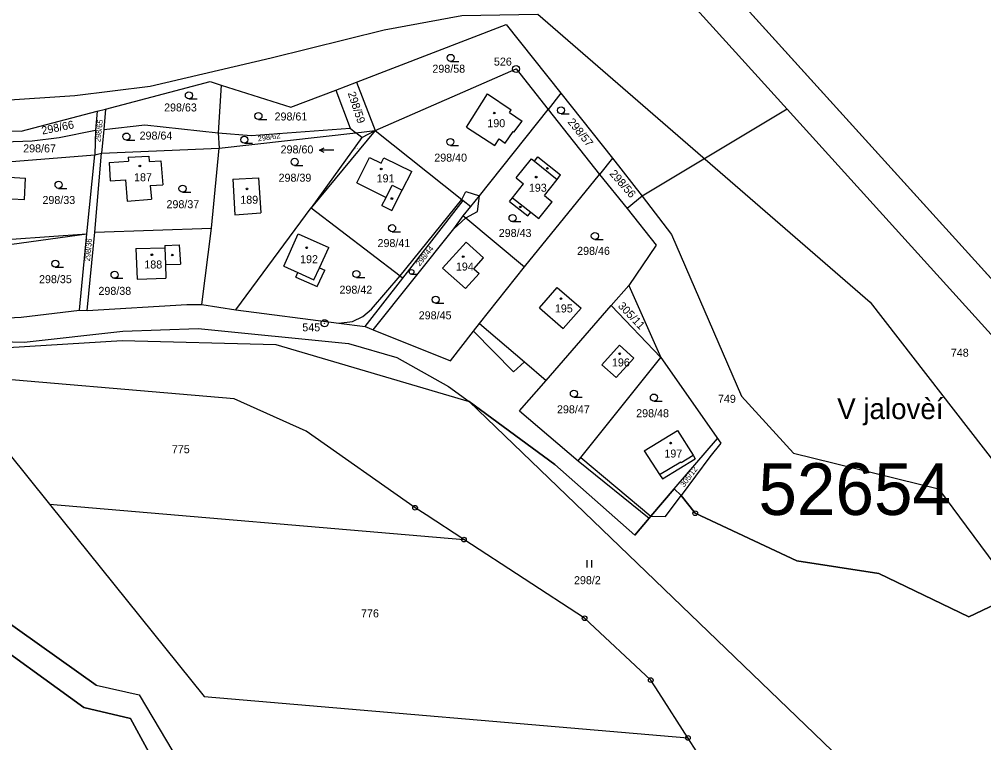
# Model space of a CAD drawing. Extents: x -725765 to -723182, y -1052705 to -1049154.
# Drawn here: x -723752.1 to -723547.3, y -1051559.5 to -1051405.8 of the extents above; entities that cross this region are included whole.
import ezdxf

# ---------------------------------------------------------------- set-up
doc = ezdxf.new("R2010")
doc.units = 0
for name, color, linetype in [('Vrstva 1', 7, 'Continuous'), ('Vrstva 13', 7, 'Continuous'), ('Vrstva 15', 7, 'Continuous'), ('Vrstva 16', 7, 'Continuous'), ('Vrstva 17', 7, 'Continuous'), ('Vrstva 18', 7, 'Continuous'), ('Vrstva 19', 7, 'Continuous'), ('Vrstva 25', 7, 'Continuous'), ('Vrstva 4', 7, 'Continuous'), ('Vrstva 52', 7, 'Continuous'), ('Vrstva 53', 7, 'Continuous')]:
    doc.layers.add(name, color=color, linetype=linetype)

msp = doc.modelspace()

# ---------------------------------------------------------------- linework, layer by layer
at = {"layer": 'Vrstva 1'}
for points in [[(-723589.08, -1051424.9), (-723679.72, -1051324.79)], [(-723680.51, -1051419.11), (-723648.75, -1051406.89)], [(-723648.75, -1051406.89), (-723637.16, -1051421.5)], [(-723676.57, -1051429.42), (-723646.65, -1051416.34)], [(-723646.65, -1051416.34), (-723639.87, -1051424.92)], [(-723733.84, -1051424.85), (-723711.6, -1051419.02)], [(-723711.6, -1051419.02), (-723709.27, -1051419.76)], [(-723709.27, -1051419.76), (-723709.93, -1051429.92)], [(-723709.27, -1051419.76), (-723694.45, -1051424.48)], [(-723684.94, -1051420.82), (-723680.51, -1051419.11)], [(-723680.51, -1051419.11), (-723676.57, -1051429.42)], [(-723694.45, -1051424.48), (-723684.94, -1051420.82)], [(-723684.94, -1051420.82), (-723681.85, -1051428.93)], [(-723657.21, -1051428.67), (-723652.73, -1051421.59)], [(-723652.73, -1051421.59), (-723647.66, -1051424.99)], [(-723637.16, -1051421.5), (-723639.87, -1051424.92)], [(-723637.16, -1051421.5), (-723626.2, -1051435.31)], [(-723751.73, -1051429.55), (-723735.61, -1051425.32)], [(-723735.61, -1051425.32), (-723735.96, -1051429.31)], [(-723735.61, -1051425.32), (-723733.84, -1051424.85)], [(-723733.84, -1051424.85), (-723734.2, -1051429.17)], [(-723654.45, -1051443.3), (-723639.87, -1051424.92)], [(-723648.06, -1051425.57), (-723647.66, -1051424.99)], [(-723648.06, -1051425.57), (-723645.35, -1051427.39)], [(-723639.87, -1051424.92), (-723628.93, -1051438.73)], [(-723589.08, -1051424.9), (-723619.84, -1051443.33)], [(-723512.61, -1051509.36), (-723589.08, -1051424.9)], [(-723734.2, -1051429.17), (-723725.45, -1051428.18)], [(-723725.45, -1051428.18), (-723709.93, -1051429.92)], [(-723657.21, -1051428.67), (-723651.18, -1051432.56)], [(-723647.12, -1051429.76), (-723645.35, -1051427.39)], [(-723759.26, -1051429.49), (-723751.73, -1051429.55)], [(-723743.64, -1051430.89), (-723735.96, -1051429.31)], [(-723735.96, -1051429.31), (-723736.13, -1051434.61)], [(-723734.2, -1051429.17), (-723734.65, -1051434.25)], [(-723709.93, -1051429.92), (-723709.67, -1051433.14)], [(-723709.93, -1051429.92), (-723702.92, -1051430.44)], [(-723709.67, -1051433.14), (-723680.68, -1051429.88)], [(-723702.92, -1051430.44), (-723681.85, -1051428.93)], [(-723676.57, -1051429.42), (-723690.19, -1051445.83)], [(-723681.85, -1051428.93), (-723680.68, -1051429.88)], [(-723680.68, -1051429.88), (-723676.57, -1051429.42)], [(-723679.41, -1051430.91), (-723680.68, -1051429.88)], [(-723676.57, -1051429.42), (-723658.16, -1051444.07)], [(-723648.96, -1051432.13), (-723647.29, -1051429.65)], [(-723647.29, -1051429.65), (-723647.12, -1051429.76)], [(-723759.54, -1051431.99), (-723749.44, -1051431.61)], [(-723749.44, -1051431.61), (-723743.64, -1051430.89)], [(-723679.41, -1051430.91), (-723690.19, -1051445.83)], [(-723651.18, -1051432.56), (-723650.22, -1051431.15)], [(-723650.22, -1051431.15), (-723648.96, -1051432.13)], [(-723760.04, -1051436.48), (-723736.13, -1051434.61)], [(-723737.77, -1051451.4), (-723736.13, -1051434.61)], [(-723736.13, -1051451.04), (-723734.65, -1051434.25)], [(-723736.13, -1051434.61), (-723734.65, -1051434.25)], [(-723734.65, -1051434.25), (-723709.67, -1051433.14)], [(-723729, -1051435.04), (-723724.66, -1051434.83)], [(-723724.66, -1051434.83), (-723724.59, -1051435.98)], [(-723710.18, -1051438.34), (-723709.67, -1051433.14)], [(-723733.09, -1051436.24), (-723728.93, -1051435.89)], [(-723733.09, -1051436.24), (-723732.85, -1051440.12)], [(-723729, -1051435.04), (-723728.93, -1051435.89)], [(-723724.59, -1051435.98), (-723722.05, -1051435.83)], [(-723722.05, -1051435.83), (-723721.68, -1051440.98)], [(-723680.44, -1051440.51), (-723677.75, -1051435.15)], [(-723677.75, -1051435.15), (-723675.3, -1051436.37)], [(-723675.3, -1051436.37), (-723674.71, -1051435.19)], [(-723674.71, -1051435.19), (-723668.79, -1051438.12)], [(-723646.62, -1051439.49), (-723643.38, -1051435.4)], [(-723643.38, -1051435.4), (-723642.76, -1051435.9)], [(-723642.76, -1051435.9), (-723642.03, -1051435.01)], [(-723642.03, -1051435.01), (-723637.19, -1051438.84)], [(-723626.2, -1051435.31), (-723628.93, -1051438.73)], [(-723626.2, -1051435.31), (-723619.84, -1051443.33)], [(-723711.34, -1051450.16), (-723710.18, -1051438.34)], [(-723670.84, -1051442.12), (-723668.79, -1051438.12)], [(-723644.88, -1051458.37), (-723628.93, -1051438.73)], [(-723637.95, -1051439.81), (-723637.19, -1051438.84)], [(-723628.93, -1051438.73), (-723623.06, -1051445.95)], [(-723759.19, -1051439.04), (-723750.8, -1051439.52)], [(-723751.05, -1051444.1), (-723750.8, -1051439.52)], [(-723732.85, -1051440.12), (-723729.56, -1051439.89)], [(-723729.56, -1051439.89), (-723729.25, -1051444.41)], [(-723724.33, -1051441.09), (-723721.68, -1051440.98)], [(-723706.82, -1051439.76), (-723701.32, -1051439.44)], [(-723706.82, -1051439.76), (-723706.4, -1051447.36)], [(-723701.32, -1051439.44), (-723700.88, -1051446.93)], [(-723680.44, -1051440.51), (-723674.24, -1051443.63)], [(-723647.41, -1051443.68), (-723645.05, -1051440.75)], [(-723646.62, -1051439.49), (-723645.05, -1051440.75)], [(-723640.63, -1051443.24), (-723637.95, -1051439.81)], [(-723724.33, -1051441.09), (-723724.08, -1051443.97)], [(-723673.03, -1051446.38), (-723670.84, -1051442.12)], [(-723753.78, -1051443.91), (-723751.05, -1051444.1)], [(-723729.25, -1051444.41), (-723724.08, -1051443.97)], [(-723675.13, -1051445.31), (-723674.24, -1051443.63)], [(-723670.69, -1051460.75), (-723657.86, -1051444.31)], [(-723658.16, -1051444.07), (-723657.86, -1051444.31)], [(-723657.86, -1051444.31), (-723656.29, -1051445.56)], [(-723656.29, -1051445.56), (-723654.45, -1051443.3)], [(-723648.03, -1051444.46), (-723647.41, -1051443.68)], [(-723648.03, -1051444.46), (-723644.15, -1051447.53)], [(-723641.79, -1051448.12), (-723638.97, -1051444.55)], [(-723640.63, -1051443.24), (-723638.97, -1051444.55)], [(-723619.84, -1051443.33), (-723623.06, -1051445.95)], [(-723619.84, -1051443.33), (-723613.68, -1051451.51)], [(-723706.4, -1051447.36), (-723700.88, -1051446.93)], [(-723706.16, -1051467.53), (-723690.19, -1051445.83)], [(-723690.19, -1051445.83), (-723671.28, -1051460.3)], [(-723675.13, -1051445.31), (-723673.03, -1051446.38)], [(-723657.89, -1051447.51), (-723656.29, -1051445.56)], [(-723644.15, -1051447.53), (-723643.51, -1051446.76)], [(-723643.51, -1051446.76), (-723641.79, -1051448.12)], [(-723623.06, -1051445.95), (-723616.9, -1051453.76)], [(-723659.87, -1051450.29), (-723657.89, -1051447.51)], [(-723657.89, -1051447.51), (-723657.32, -1051447.99)], [(-723657.32, -1051447.99), (-723644.88, -1051458.37)], [(-723737.7, -1051467.62), (-723736.13, -1051451.04)], [(-723736.13, -1051451.04), (-723711.34, -1051450.16)], [(-723713.36, -1051466.39), (-723711.34, -1051450.16)], [(-723677.03, -1051471.79), (-723659.87, -1051450.29)], [(-723761.87, -1051453.08), (-723737.77, -1051451.4)], [(-723739.33, -1051467.58), (-723737.77, -1051451.4)], [(-723695.95, -1051458.23), (-723692.95, -1051451.37)], [(-723692.95, -1051451.37), (-723686.44, -1051454.27)], [(-723662.24, -1051458.63), (-723657.27, -1051453.12)], [(-723657.27, -1051453.12), (-723653.54, -1051456.45)], [(-723613.68, -1051451.51), (-723598.78, -1051485.83)], [(-723727.37, -1051454.51), (-723721.23, -1051454.36)], [(-723727.37, -1051454.51), (-723727.14, -1051460.98)], [(-723721.25, -1051453.81), (-723718.2, -1051453.72)], [(-723721.25, -1051453.81), (-723721.23, -1051454.36)], [(-723718.2, -1051453.72), (-723717.93, -1051457.8)], [(-723688.4, -1051458.58), (-723686.44, -1051454.27)], [(-723616.9, -1051453.76), (-723622.72, -1051462.36)], [(-723655.63, -1051458.78), (-723653.54, -1051456.45)], [(-723721.12, -1051457.9), (-723717.93, -1051457.8)], [(-723721.12, -1051457.9), (-723721.03, -1051460.79)], [(-723695.95, -1051458.23), (-723692.97, -1051459.61)], [(-723688.91, -1051462.57), (-723687.27, -1051459.05)], [(-723688.4, -1051458.58), (-723687.27, -1051459.05)], [(-723662.24, -1051458.63), (-723657.37, -1051462.96)], [(-723655.63, -1051458.78), (-723654.51, -1051459.79)], [(-723654.41, -1051470.42), (-723644.88, -1051458.37)], [(-723727.14, -1051460.98), (-723721.03, -1051460.79)], [(-723693.44, -1051460.54), (-723692.97, -1051459.61)], [(-723693.44, -1051460.54), (-723688.91, -1051462.57)], [(-723678.72, -1051471.04), (-723670.69, -1051460.75)], [(-723671.28, -1051460.3), (-723670.69, -1051460.75)], [(-723657.37, -1051462.96), (-723654.51, -1051459.79)], [(-723641.7, -1051467.11), (-723637.91, -1051462.78)], [(-723637.91, -1051462.78), (-723632.86, -1051467.14)], [(-723626.47, -1051466.56), (-723622.72, -1051462.36)], [(-723622.72, -1051462.36), (-723615.88, -1051477.67)], [(-723751.71, -1051469.1), (-723739.33, -1051467.58)], [(-723739.33, -1051467.58), (-723737.7, -1051467.62)], [(-723737.7, -1051467.62), (-723716.54, -1051466.37)], [(-723716.54, -1051466.37), (-723713.36, -1051466.39)], [(-723713.36, -1051466.39), (-723706.16, -1051467.53)], [(-723706.16, -1051467.53), (-723684.3, -1051470.33)], [(-723641.7, -1051467.11), (-723636.68, -1051471.5)], [(-723640.24, -1051482.51), (-723626.47, -1051466.56)], [(-723636.68, -1051471.5), (-723632.86, -1051467.14)], [(-723626.47, -1051466.56), (-723615.88, -1051477.67)], [(-723763.16, -1051469.61), (-723751.71, -1051469.1)], [(-723730.17, -1051472.08), (-723714.13, -1051471.46)], [(-723714.13, -1051471.46), (-723682.21, -1051474.64)], [(-723684.3, -1051470.33), (-723678.72, -1051471.04)], [(-723678.72, -1051471.04), (-723677.03, -1051471.79)], [(-723655.7, -1051472.07), (-723654.41, -1051470.42)], [(-723654.41, -1051470.42), (-723644.83, -1051478.59)], [(-723751.13, -1051474.35), (-723730.17, -1051472.08)], [(-723677.03, -1051471.79), (-723660.56, -1051478.32)], [(-723660.56, -1051478.32), (-723655.7, -1051472.07)], [(-723770.72, -1051476.53), (-723730.31, -1051474.06)], [(-723763.53, -1051474.03), (-723751.13, -1051474.35)], [(-723730.31, -1051474.06), (-723697.64, -1051474.89)], [(-723697.64, -1051474.89), (-723656.62, -1051487.01)], [(-723682.21, -1051474.64), (-723671.97, -1051477.65)], [(-723628.47, -1051479.21), (-723624.71, -1051475.01)], [(-723624.71, -1051475.01), (-723621.65, -1051477.8)], [(-723671.97, -1051477.65), (-723661, -1051483.8)], [(-723632.89, -1051498.9), (-723615.88, -1051477.67)], [(-723625.37, -1051481.88), (-723621.65, -1051477.8)], [(-723615.88, -1051477.67), (-723603.14, -1051495.87)], [(-723644.83, -1051478.59), (-723640.24, -1051482.51)], [(-723628.47, -1051479.21), (-723625.37, -1051481.88)], [(-723767.94, -1051481.2), (-723745.73, -1051508.83)], [(-723706.54, -1051486.44), (-723767.94, -1051481.2)], [(-723661, -1051483.8), (-723656.62, -1051487.01)], [(-723645.9, -1051489), (-723640.24, -1051482.51)], [(-723598.78, -1051485.83), (-723587.77, -1051497.95)], [(-723691.23, -1051493.31), (-723706.54, -1051486.44)], [(-723656.62, -1051487.01), (-723638.4, -1051500.35)], [(-723656.62, -1051487.01), (-723575.76, -1051564.86)], [(-723645.9, -1051489), (-723633.43, -1051499.58)], [(-723668.1, -1051509.58), (-723691.23, -1051493.31)], [(-723619.47, -1051497.5), (-723612.4, -1051493.13)], [(-723612.4, -1051493.13), (-723609.06, -1051498.41)], [(-723613.05, -1051505.55), (-723603.87, -1051494.83)], [(-723603.14, -1051495.87), (-723605.49, -1051498.72)], [(-723603.87, -1051494.83), (-723603.14, -1051495.87)], [(-723619.47, -1051497.5), (-723616.19, -1051502.47)], [(-723587.77, -1051497.95), (-723556.95, -1051505.58)], [(-723638.4, -1051500.35), (-723621.46, -1051515.37)], [(-723633.43, -1051499.58), (-723632.89, -1051498.9)], [(-723633.43, -1051499.58), (-723618.41, -1051511.81)], [(-723615.55, -1051503.44), (-723608.6, -1051499.14)], [(-723605.49, -1051498.72), (-723611.59, -1051506.99)], [(-723609.06, -1051498.41), (-723608.6, -1051499.14)], [(-723616.19, -1051502.47), (-723615.55, -1051503.44)], [(-723618.04, -1051511.38), (-723613.05, -1051505.55)], [(-723613.05, -1051505.55), (-723611.59, -1051506.99)], [(-723556.95, -1051505.58), (-723540.54, -1051527.73)], [(-723611.59, -1051506.99), (-723608.62, -1051510.73)], [(-723745.73, -1051508.83), (-723712.87, -1051549.7)], [(-723745.73, -1051508.83), (-723657.72, -1051516.34)], [(-723665.77, -1051511.09), (-723668.1, -1051509.58)], [(-723657.72, -1051516.34), (-723665.77, -1051511.09)], [(-723621.46, -1051515.37), (-723618.41, -1051511.81)], [(-723618.41, -1051511.81), (-723618.04, -1051511.38)], [(-723608.62, -1051510.73), (-723587.06, -1051520.84)], [(-723632.09, -1051533.05), (-723657.72, -1051516.34)], [(-723587.06, -1051520.84), (-723569.65, -1051523.55)], [(-723569.65, -1051523.55), (-723550.5, -1051532.75)], [(-723735.81, -1051547.23), (-723760.44, -1051529.74)], [(-723550.5, -1051532.75), (-723544.71, -1051530.01)], [(-723618.06, -1051546.2), (-723632.09, -1051533.05)], [(-723738.43, -1051552.03), (-723761.92, -1051534.99)], [(-723735.81, -1051547.23), (-723726.68, -1051549.29)], [(-723616.36, -1051548.82), (-723618.06, -1051546.2)], [(-723726.68, -1051549.29), (-723706.61, -1051583.2)], [(-723610.16, -1051558.47), (-723616.36, -1051548.82)], [(-723712.87, -1051549.7), (-723610.16, -1051558.47)], [(-723728.55, -1051554.37), (-723738.43, -1051552.03)], [(-723711.06, -1051586.5), (-723728.55, -1051554.37)], [(-723601.23, -1051572.36), (-723610.16, -1051558.47)]]:
    msp.add_lwpolyline(points, dxfattribs=at)
at = {"layer": 'Vrstva 13'}
msp.add_lwpolyline([(-723506.17, -1051504.56), (-723672.97, -1051320.32)], dxfattribs=at)
at = {"layer": 'Vrstva 25'}
for points in [[(-723660.54, -1051414.73), (-723658.79, -1051414.73)], [(-723716.13, -1051422.69), (-723714.38, -1051422.69)], [(-723637.1, -1051425.87), (-723635.35, -1051425.87)], [(-723701.36, -1051427.07), (-723699.61, -1051427.07)], [(-723729.39, -1051431.44), (-723727.64, -1051431.44)], [(-723704.35, -1051432.11), (-723702.6, -1051432.11)], [(-723660.6, -1051432.59), (-723658.85, -1051432.59)], [(-723687.38, -1051434.08), (-723688.38, -1051433.59), (-723687.38, -1051433.08)], [(-723685.38, -1051433.56), (-723688.38, -1051433.59)], [(-723693.67, -1051436.81), (-723691.92, -1051436.81)], [(-723743.8, -1051441.7), (-723742.05, -1051441.7)], [(-723717.48, -1051442.51), (-723715.73, -1051442.51)], [(-723647.4, -1051448.77), (-723645.65, -1051448.77)], [(-723672.97, -1051450.91), (-723671.22, -1051450.91)], [(-723629.92, -1051452.57), (-723628.17, -1051452.57)], [(-723744.49, -1051458.46), (-723742.74, -1051458.46)], [(-723731.91, -1051460.82), (-723730.16, -1051460.82)], [(-723680.55, -1051460.65), (-723678.8, -1051460.65)], [(-723668.85, -1051459.95), (-723667.68, -1051459.95)], [(-723663.73, -1051466.1), (-723661.98, -1051466.1)], [(-723634.37, -1051486.07), (-723632.62, -1051486.07)], [(-723617.38, -1051486.9), (-723615.63, -1051486.9)], [(-723631.58, -1051522.24), (-723631.58, -1051520.74)], [(-723630.54, -1051522.24), (-723630.54, -1051520.74)]]:
    msp.add_lwpolyline(points, dxfattribs=at)
for centre, radius in [((-723660.54, -1051413.98), 0.75), ((-723646.65, -1051416.34), 0.75), ((-723646.65, -1051416.34), 0.032), ((-723716.13, -1051421.94), 0.75), ((-723637.1, -1051425.12), 0.75), ((-723701.36, -1051426.32), 0.75), ((-723651.28, -1051425.69), 0.175), ((-723729.39, -1051430.69), 0.75), ((-723704.35, -1051431.36), 0.75), ((-723660.6, -1051431.84), 0.75), ((-723726.53, -1051436.94), 0.175), ((-723693.67, -1051436.06), 0.75), ((-723675.28, -1051437.58), 0.175), ((-723640, -1051437.45), 0.175), ((-723743.8, -1051440.95), 0.75), ((-723642.38, -1051439.31), 0.175), ((-723717.48, -1051441.76), 0.75), ((-723703.77, -1051441.81), 0.175), ((-723673.02, -1051443.87), 0.175), ((-723645.75, -1051445.65), 0.175), ((-723647.4, -1051448.02), 0.75), ((-723672.97, -1051450.16), 0.75), ((-723629.92, -1051451.82), 0.75), ((-723691.11, -1051454.33), 0.175), ((-723744.49, -1051457.71), 0.75), ((-723723.98, -1051455.82), 0.175), ((-723719.65, -1051455.88), 0.175), ((-723657.88, -1051456.22), 0.175), ((-723731.91, -1051460.07), 0.75), ((-723680.55, -1051459.9), 0.75), ((-723668.85, -1051459.45), 0.503), ((-723663.73, -1051465.35), 0.75), ((-723637.1, -1051465.14), 0.175), ((-723687.32, -1051470.36), 0.75), ((-723687.32, -1051470.36), 0.032), ((-723624.65, -1051476.86), 0.175), ((-723634.37, -1051485.32), 0.75), ((-723617.38, -1051486.15), 0.75), ((-723613.84, -1051495.84), 0.175), ((-723668.1, -1051509.58), 0.5), ((-723668.1, -1051509.58), 0.032), ((-723608.62, -1051510.73), 0.5), ((-723608.62, -1051510.73), 0.032), ((-723657.72, -1051516.34), 0.5), ((-723657.72, -1051516.34), 0.032), ((-723632.09, -1051533.05), 0.5), ((-723632.09, -1051533.05), 0.032), ((-723618.06, -1051546.2), 0.5), ((-723618.06, -1051546.2), 0.032), ((-723610.16, -1051558.47), 0.5), ((-723610.16, -1051558.47), 0.032)]:
    msp.add_circle(centre, radius, dxfattribs=at)
at = {"layer": 'Vrstva 4'}
for points in [[(-723679.41, -1051430.91), (-723676.57, -1051429.42)], [(-723642.76, -1051435.9), (-723637.95, -1051439.81)], [(-723674.24, -1051443.63), (-723672.93, -1051441.05)], [(-723672.93, -1051441.05), (-723670.84, -1051442.12)], [(-723658.16, -1051444.07), (-723657.35, -1051442.34)], [(-723657.35, -1051442.34), (-723654.45, -1051443.3)], [(-723671.28, -1051460.3), (-723658.16, -1051444.07)], [(-723654.81, -1051446.62), (-723654.45, -1051443.3)], [(-723647.41, -1051443.68), (-723643.51, -1051446.76)], [(-723657.32, -1051447.99), (-723654.81, -1051446.62)], [(-723659.87, -1051450.29), (-723657.32, -1051447.99)], [(-723762.03, -1051454.69), (-723737.77, -1051451.4)], [(-723721.23, -1051454.36), (-723721.12, -1051457.9)], [(-723689.58, -1051461.17), (-723688.4, -1051458.58)], [(-723692.97, -1051459.61), (-723689.58, -1051461.17)], [(-723677.38, -1051467.37), (-723671.28, -1051460.3)], [(-723679.16, -1051468.93), (-723677.38, -1051467.37)], [(-723681.35, -1051469.99), (-723679.16, -1051468.93)], [(-723684.3, -1051470.33), (-723681.35, -1051469.99)], [(-723655.7, -1051472.07), (-723647.22, -1051480.67)], [(-723647.22, -1051480.67), (-723644.83, -1051478.59)], [(-723632.89, -1051498.9), (-723618.04, -1051511.38)], [(-723616.19, -1051502.47), (-723611.64, -1051499.79)], [(-723611.64, -1051499.79), (-723611.56, -1051499.92)], [(-723611.56, -1051499.92), (-723609.06, -1051498.41)], [(-723614.94, -1051511.43), (-723611.59, -1051506.99)], [(-723618.04, -1051511.38), (-723614.94, -1051511.43)]]:
    msp.add_lwpolyline(points, dxfattribs=at)
at = {"layer": 'Vrstva 52'}
for points in [[(-724052.94, -1051264.55), (-724048.1, -1051266.31), (-723994.84, -1051296.21), (-723962.81, -1051312.97), (-723926.39, -1051332.1), (-723911.42, -1051348.47), (-723895.29, -1051392.3), (-723884.86, -1051418.68), (-723868.34, -1051447.67), (-723828.41, -1051486.92), (-723818.84, -1051492.05), (-723810.19, -1051499.57), (-723787.98, -1051513.89), (-723769.62, -1051527.53), (-723760.44, -1051529.74), (-723735.81, -1051547.23), (-723726.68, -1051549.29), (-723706.61, -1051583.2)], [(-724050.47, -1051269.54), (-723997.26, -1051299.64), (-723964.68, -1051317.59), (-723929.12, -1051336.03), (-723916.43, -1051350.67), (-723899.09, -1051393.61), (-723888.79, -1051420.29), (-723872.12, -1051450.91), (-723831.46, -1051490.09), (-723822.26, -1051497.46), (-723811.9, -1051505.06), (-723789.38, -1051517.54), (-723771.8, -1051531.34), (-723761.92, -1051534.99), (-723738.43, -1051552.03), (-723728.55, -1051554.37), (-723711.06, -1051586.5), (-723687.84, -1051594.09), (-723669.45, -1051611.26), (-723662.6, -1051628), (-723652.76, -1051646.8), (-723641.04, -1051681.92), (-723643.18, -1051682.48), (-723641.32, -1051689.61)], [(-723797.67, -1051320.64), (-723794.81, -1051326.76), (-723811.35, -1051338.44), (-723823.52, -1051347.4), (-723813.63, -1051365), (-723796.31, -1051397), (-723789.63, -1051409), (-723784.13, -1051415), (-723777.5, -1051420), (-723769.69, -1051422), (-723756.38, -1051423), (-723740.38, -1051422), (-723724.38, -1051420), (-723698.63, -1051414), (-723674.63, -1051408), (-723658.19, -1051405), (-723642.02, -1051404.66)], [(-723623.01, -1051375.5), (-723506.17, -1051504.56), (-723491.66, -1051528.5), (-723472.51, -1051550.6), (-723475.49, -1051552.83), (-723444.61, -1051592.55), (-723412.71, -1051648.87), (-723410.63, -1051651.78), (-723383.37, -1051694.64), (-723347.68, -1051736.75), (-723332.74, -1051719.45), (-723298.77, -1051676.97), (-723288.04, -1051666.17), (-723190.91, -1051734.62), (-723187.06, -1051778.38), (-723184.65, -1051850.16), (-723185.86, -1051869.24), (-723183.9, -1051911.02)], [(-723642.02, -1051404.66), (-723571.43, -1051465.9), (-723532.53, -1051516.07), (-723504.22, -1051561.73), (-723499.33, -1051575.42), (-723494.15, -1051584.88), (-723477.03, -1051612.07), (-723444.82, -1051679.52), (-723411.59, -1051732.89), (-723358.23, -1051770.14), (-723354.02, -1051772.21)], [(-723601.23, -1051572.36), (-723610.16, -1051558.47), (-723616.36, -1051548.82), (-723618.06, -1051546.2), (-723632.09, -1051533.05), (-723657.72, -1051516.34), (-723665.77, -1051511.09), (-723668.1, -1051509.58), (-723691.23, -1051493.31), (-723706.54, -1051486.44), (-723767.94, -1051481.2)], [(-723544.71, -1051530.01), (-723550.5, -1051532.75), (-723569.65, -1051523.55), (-723587.06, -1051520.84), (-723608.62, -1051510.73), (-723611.59, -1051506.99), (-723613.05, -1051505.55), (-723618.04, -1051511.38), (-723618.41, -1051511.81), (-723621.46, -1051515.37), (-723638.4, -1051500.35), (-723656.62, -1051487.01), (-723575.76, -1051564.86), (-723565.96, -1051581.15), (-723558.11, -1051601.55), (-723549.99, -1051631.01), (-723521.75, -1051711.32)]]:
    msp.add_lwpolyline(points, dxfattribs=at)

# ---------------------------------------------------------------- texts
at = {"layer": 'Vrstva 15'}
msp.add_text('V jalovèí', height=4.4, dxfattribs=at).set_placement((-723578.46, -1051490.73))
at = {"layer": 'Vrstva 16'}
msp.add_text('298/60', height=1.7, dxfattribs=at).set_placement((-723696.65, -1051434.28))
at = {"layer": 'Vrstva 17'}
for s, p in [('526', (-723651.35, -1051415.62)), ('545', (-723692.04, -1051472.08))]:
    msp.add_text(s, height=1.7, dxfattribs=at).set_placement(p)
at = {"layer": 'Vrstva 18'}
for s, height, p in [('298/58', 1.7, (-723664.42, -1051417.13)), ('298/63', 1.7, (-723721.39, -1051425.36)), ('298/61', 1.7, (-723697.93, -1051427.28)), ('298/64', 1.7, (-723726.59, -1051431.34)), ('298/67', 1.7, (-723751.31, -1051434.06)), ('298/60', 0.1, (-723680.69, -1051433.32)), ('298/40', 1.7, (-723664.02, -1051436.02)), ('298/39', 1.7, (-723697.08, -1051440.29)), ('298/33', 1.7, (-723747.22, -1051445.03)), ('298/37', 1.7, (-723720.88, -1051445.92)), ('298/43', 1.7, (-723650.33, -1051452.03)), ('298/41', 1.7, (-723676.07, -1051454.18)), ('298/46', 1.7, (-723633.68, -1051455.83)), ('298/35', 1.7, (-723747.95, -1051461.85)), ('298/38', 1.7, (-723735.33, -1051464.33)), ('298/42', 1.7, (-723684.15, -1051464.08)), ('298/45', 1.7, (-723667.32, -1051469.53)), ('748', 1.7, (-723554.33, -1051477.47)), ('749', 1.7, (-723603.78, -1051487.27)), ('298/47', 1.7, (-723637.96, -1051489.5)), ('298/48', 1.7, (-723621.14, -1051490.33)), ('775', 1.7, (-723719.74, -1051497.98)), ('298/2', 1.7, (-723634.35, -1051525.81)), ('776', 1.7, (-723679.57, -1051532.86))]:
    msp.add_text(s, height=height, dxfattribs=at).set_placement(p)
for s, height, rotation, p in [('298/59', 1.7, 288.4023, (-723682.42, -1051421.47)), ('298/66', 1.7, 11.3001, (-723747.23, -1051430.28)), ('298/65', 1.17, 83.2007, (-723734.93, -1051431.92)), ('298/57', 1.7, 308.9025, (-723635.81, -1051427.63)), ('298/62', 1.14, 8.1001, (-723701.42, -1051431.71)), ('298/56', 1.7, 311.2025, (-723626.91, -1051438.66)), ('298/36', 1.19, 84.5007, (-723737.15, -1051457.25)), ('298/44', 1.19, 51.4004, (-723667.11, -1051458.33)), ('305/11', 1.7, 313.6025, (-723625.13, -1051466.8)), ('305/12', 1.19, 53.3004, (-723610.95, -1051505.28))]:
    msp.add_text(s, height=height, rotation=rotation, dxfattribs=at).set_placement(p)
at = {"layer": 'Vrstva 19'}
for s, p in [('190', (-723652.75, -1051428.71)), ('187', (-723727.77, -1051440.19)), ('191', (-723676.26, -1051440.43)), ('193', (-723643.93, -1051442.42)), ('189', (-723705.21, -1051444.97)), ('188', (-723725.59, -1051458.73)), ('192', (-723692.51, -1051457.6)), ('194', (-723659.43, -1051459.17)), ('195', (-723638.41, -1051468.07)), ('196', (-723626.29, -1051479.54)), ('197', (-723615.16, -1051498.9))]:
    msp.add_text(s, height=1.7, dxfattribs=at).set_placement(p)
at = {"layer": 'Vrstva 53'}
msp.add_text('52654', height=11, dxfattribs=at).set_placement((-723595.2, -1051511.1))

doc.saveas('drawing.dxf')
